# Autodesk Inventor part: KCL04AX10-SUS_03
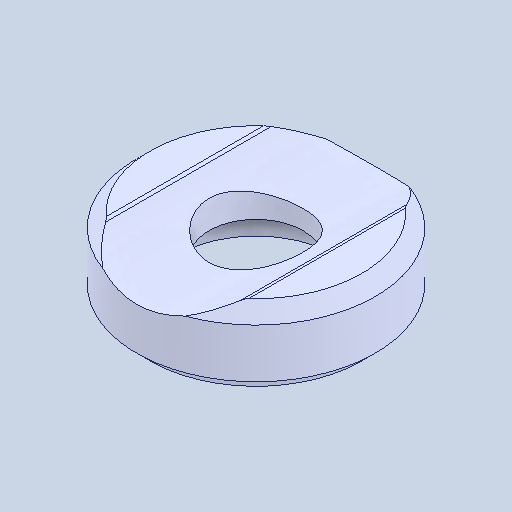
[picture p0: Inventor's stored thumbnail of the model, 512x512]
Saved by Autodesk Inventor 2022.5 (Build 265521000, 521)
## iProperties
Created: 2024-08
Part Number: KCL04AX10-SUS_03
Material: 一般
Document SubType Name: Modeling
Designer: ImaoCorp
Density: 1 g/cm^3
Appearance: 既定
Author: ImaoCorp
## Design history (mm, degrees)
feature "KCL04AX10-SUS_03"
node "ソリッド1"
